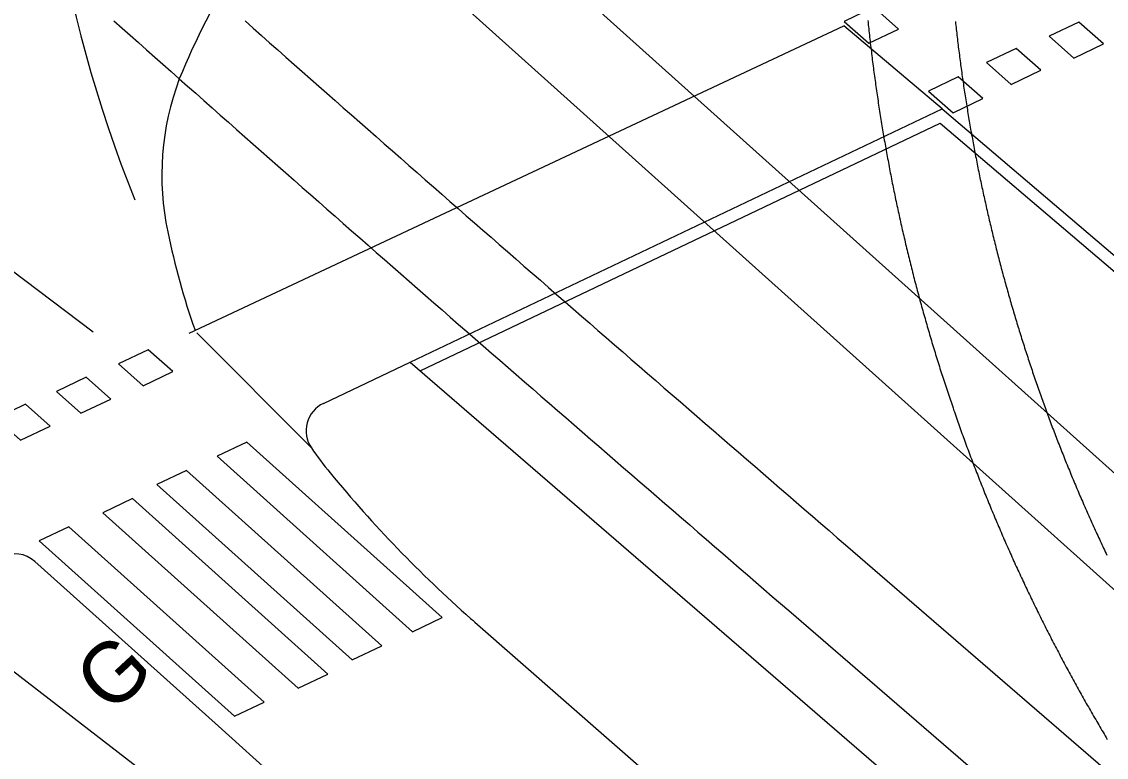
# Model space of a CAD drawing. Extents: x 81617 to 82144, y 454649 to 455150.
# Drawn here: x 81697.46 to 81715.37, y 454720.05 to 454732.19 of the extents above; entities that cross this region are included whole.
import ezdxf

# ---------------------------------------------------------------- set-up
doc = ezdxf.new("R2010")
doc.units = 0
doc.layers.add('B-WE-OG-TOPOGRAFIE-G', color=7, linetype='Continuous')
doc.layers.add('B-WE-VW-MARKERING-G', color=7, linetype='Continuous')

msp = doc.modelspace()

# ---------------------------------------------------------------- linework, layer by layer
at = {"layer": 'B-WE-OG-TOPOGRAFIE-G'}
for p, q in [((81712.656, 454730.753), (81711.029, 454732.123)), ((81703.871, 454726.575), (81712.656, 454730.753)), ((81712.656, 454730.753), (81722.86, 454722.067)), ((81704.037, 454726.432), (81712.624, 454730.516)), ((81712.624, 454730.516), (81722.73, 454721.915)), ((81702.24, 454725.16), (81700.349, 454727.06)), ((81702.438, 454725.893), (81703.871, 454726.575)), ((81703.871, 454726.575), (81730.855, 454703.267)), ((81700.649, 454720.614), (81697.672, 454723.285)), ((81699.533, 454719.756), (81696.366, 454722.2)), ((81704.288, 454717.349), (81700.649, 454720.614))]:
    msp.add_line(p, q, dxfattribs=at)
for points in [[(81733.293, 454708.784), (81733.175, 454708.889), (81733.058, 454708.994), (81732.94, 454709.1), (81732.94, 454709.1), (81698.035, 454740.405), (81698.035, 454740.405), (81697.901, 454740.525), (81697.766, 454740.646), (81697.632, 454740.766), (81697.498, 454740.887), (81697.364, 454741.007)], [(81733.393, 454706.767), (81733.276, 454706.872), (81733.158, 454706.977), (81733.04, 454707.083), (81732.923, 454707.188), (81732.805, 454707.294), (81732.688, 454707.399), (81732.57, 454707.504), (81732.452, 454707.61), (81732.335, 454707.715), (81732.217, 454707.821), (81732.1, 454707.926), (81731.982, 454708.032), (81731.982, 454708.032), (81697.077, 454739.337)], [(81698.978, 454732.209), (81699.113, 454732.089), (81699.248, 454731.969), (81699.383, 454731.849), (81699.518, 454731.729), (81699.653, 454731.609), (81699.788, 454731.49), (81699.923, 454731.37), (81700.058, 454731.25), (81700.194, 454731.131), (81700.329, 454731.011), (81700.464, 454730.891), (81700.599, 454730.772), (81700.735, 454730.652), (81700.87, 454730.533), (81701.005, 454730.413), (81701.141, 454730.294), (81701.276, 454730.174), (81701.412, 454730.055), (81701.547, 454729.935), (81701.683, 454729.816), (81701.818, 454729.697), (81701.954, 454729.577), (81702.089, 454729.458), (81702.225, 454729.339), (81702.36, 454729.22), (81702.496, 454729.101), (81702.632, 454728.981), (81702.767, 454728.862), (81702.903, 454728.743), (81703.039, 454728.624), (81703.175, 454728.505), (81703.31, 454728.386), (81703.446, 454728.267), (81703.582, 454728.148), (81703.718, 454728.03), (81703.854, 454727.911), (81703.99, 454727.792), (81704.126, 454727.673), (81704.262, 454727.554), (81704.398, 454727.436), (81704.534, 454727.317), (81704.67, 454727.198), (81704.806, 454727.08), (81704.806, 454727.079), (81704.942, 454726.961), (81705.078, 454726.842), (81705.214, 454726.724), (81705.351, 454726.605), (81705.487, 454726.487), (81705.623, 454726.369), (81705.759, 454726.25), (81705.895, 454726.132), (81706.031, 454726.014), (81706.168, 454725.895), (81706.304, 454725.777), (81706.44, 454725.659), (81706.576, 454725.541), (81706.713, 454725.423), (81706.849, 454725.304), (81706.985, 454725.186), (81707.122, 454725.068), (81707.258, 454724.95), (81707.394, 454724.832), (81707.531, 454724.714), (81707.667, 454724.596), (81707.804, 454724.478), (81707.94, 454724.36), (81708.076, 454724.242), (81708.213, 454724.124), (81708.349, 454724.006), (81708.486, 454723.888), (81708.622, 454723.77), (81708.758, 454723.652), (81708.895, 454723.534), (81709.031, 454723.416), (81709.168, 454723.299), (81709.304, 454723.181), (81709.441, 454723.063), (81709.577, 454722.945), (81709.713, 454722.827), (81709.85, 454722.709), (81709.986, 454722.591), (81710.123, 454722.473), (81710.123, 454722.473), (81759.251, 454680.037)], [(81701.145, 454732.205), (81701.28, 454732.086), (81701.415, 454731.966), (81701.55, 454731.847), (81701.685, 454731.728), (81701.82, 454731.608), (81701.955, 454731.489), (81702.09, 454731.37), (81702.225, 454731.25), (81702.36, 454731.131), (81702.496, 454731.012), (81702.631, 454730.893), (81702.766, 454730.774), (81702.901, 454730.655), (81703.037, 454730.536), (81703.172, 454730.417), (81703.308, 454730.298), (81703.443, 454730.179), (81703.578, 454730.06), (81703.714, 454729.941), (81703.849, 454729.822), (81703.985, 454729.703), (81704.12, 454729.585), (81704.256, 454729.466), (81704.392, 454729.347), (81704.527, 454729.228), (81704.663, 454729.11), (81704.798, 454728.991), (81704.934, 454728.872), (81705.07, 454728.754), (81705.206, 454728.635), (81705.341, 454728.517), (81705.477, 454728.398), (81705.613, 454728.28), (81705.749, 454728.161), (81705.749, 454728.161), (81705.885, 454728.043), (81706.021, 454727.925), (81706.157, 454727.806), (81706.292, 454727.688), (81706.428, 454727.57), (81706.564, 454727.452), (81706.7, 454727.334), (81706.836, 454727.215), (81706.972, 454727.097), (81707.108, 454726.979), (81707.244, 454726.861), (81707.381, 454726.743), (81707.517, 454726.625), (81707.653, 454726.507), (81707.789, 454726.389), (81707.925, 454726.271), (81708.061, 454726.153), (81708.197, 454726.035), (81708.334, 454725.917), (81708.47, 454725.799), (81708.606, 454725.681), (81708.742, 454725.563), (81708.879, 454725.445), (81709.015, 454725.327), (81709.151, 454725.209), (81709.288, 454725.092), (81709.424, 454724.974), (81709.56, 454724.856), (81709.697, 454724.738), (81709.833, 454724.62), (81709.97, 454724.502), (81710.106, 454724.384), (81710.242, 454724.266), (81710.379, 454724.149), (81710.515, 454724.031), (81710.652, 454723.913), (81710.788, 454723.795), (81710.924, 454723.677), (81711.061, 454723.559), (81711.061, 454723.559), (81760.224, 454681.093)], [(81711.428, 454732.213), (81711.432, 454732.178), (81711.435, 454732.144), (81711.439, 454732.11), (81711.443, 454732.076), (81711.446, 454732.042), (81711.45, 454732.008), (81711.454, 454731.974), (81711.458, 454731.939), (81711.462, 454731.905), (81711.465, 454731.871), (81711.469, 454731.837), (81711.473, 454731.803), (81711.477, 454731.769), (81711.481, 454731.735), (81711.486, 454731.701), (81711.49, 454731.666), (81711.494, 454731.632), (81711.498, 454731.598), (81711.502, 454731.564), (81711.507, 454731.53), (81711.511, 454731.496), (81711.515, 454731.462), (81711.52, 454731.428), (81711.524, 454731.394), (81711.529, 454731.36), (81711.533, 454731.326), (81711.538, 454731.292), (81711.543, 454731.258), (81711.547, 454731.224), (81711.552, 454731.19), (81711.557, 454731.156), (81711.561, 454731.122), (81711.566, 454731.088), (81711.571, 454731.054), (81711.576, 454731.02), (81711.581, 454730.986), (81711.586, 454730.952), (81711.591, 454730.918), (81711.596, 454730.884), (81711.601, 454730.85), (81711.606, 454730.816), (81711.612, 454730.782), (81711.617, 454730.748), (81711.622, 454730.714), (81711.627, 454730.68), (81711.633, 454730.646), (81711.638, 454730.612), (81711.644, 454730.578), (81711.649, 454730.544), (81711.655, 454730.51), (81711.66, 454730.477), (81711.666, 454730.443), (81711.671, 454730.409), (81711.677, 454730.375), (81711.683, 454730.341), (81711.689, 454730.307), (81711.694, 454730.273), (81711.7, 454730.239), (81711.706, 454730.206), (81711.712, 454730.172), (81711.718, 454730.138), (81711.724, 454730.104), (81711.73, 454730.07), (81711.736, 454730.037), (81711.742, 454730.003), (81711.748, 454729.969), (81711.755, 454729.935), (81711.761, 454729.901), (81711.767, 454729.868), (81711.773, 454729.834), (81711.78, 454729.8), (81711.786, 454729.766), (81711.793, 454729.733), (81711.799, 454729.699), (81711.806, 454729.665), (81711.812, 454729.631), (81711.819, 454729.598), (81711.826, 454729.564), (81711.832, 454729.53), (81711.839, 454729.497), (81711.846, 454729.463), (81711.853, 454729.429), (81711.859, 454729.396), (81711.866, 454729.362), (81711.873, 454729.328), (81711.88, 454729.295), (81711.887, 454729.261), (81711.894, 454729.228), (81711.901, 454729.194), (81711.909, 454729.16), (81711.916, 454729.127), (81711.923, 454729.093), (81711.93, 454729.06), (81711.937, 454729.026), (81711.945, 454728.992), (81711.952, 454728.959), (81711.96, 454728.925), (81711.967, 454728.892), (81711.975, 454728.858), (81711.982, 454728.825), (81711.99, 454728.791), (81711.997, 454728.758), (81712.005, 454728.724), (81712.013, 454728.691), (81712.02, 454728.657), (81712.028, 454728.624), (81712.036, 454728.591), (81712.044, 454728.557), (81712.052, 454728.524), (81712.06, 454728.49), (81712.068, 454728.457), (81712.076, 454728.423), (81712.084, 454728.39), (81712.092, 454728.357), (81712.1, 454728.323), (81712.108, 454728.29), (81712.116, 454728.257), (81712.125, 454728.223), (81712.133, 454728.19), (81712.141, 454728.157), (81712.15, 454728.123), (81712.158, 454728.09), (81712.167, 454728.057), (81712.175, 454728.023), (81712.184, 454727.99), (81712.192, 454727.957), (81712.201, 454727.924), (81712.209, 454727.89), (81712.218, 454727.857), (81712.227, 454727.824), (81712.236, 454727.791), (81712.244, 454727.758), (81712.253, 454727.724), (81712.262, 454727.691), (81712.271, 454727.658), (81712.28, 454727.625), (81712.289, 454727.592), (81712.298, 454727.559), (81712.307, 454727.525), (81712.316, 454727.492), (81712.325, 454727.459), (81712.335, 454727.426), (81712.344, 454727.393), (81712.353, 454727.36), (81712.363, 454727.327), (81712.372, 454727.294), (81712.381, 454727.261), (81712.391, 454727.228), (81712.4, 454727.195), (81712.41, 454727.162), (81712.419, 454727.129), (81712.429, 454727.096), (81712.439, 454727.063), (81712.448, 454727.03), (81712.458, 454726.997), (81712.468, 454726.964), (81712.478, 454726.931), (81712.487, 454726.898), (81712.497, 454726.865), (81712.507, 454726.832), (81712.517, 454726.8), (81712.527, 454726.767), (81712.537, 454726.734), (81712.547, 454726.701), (81712.557, 454726.668), (81712.568, 454726.635), (81712.578, 454726.603), (81712.588, 454726.57), (81712.598, 454726.537), (81712.609, 454726.504), (81712.619, 454726.472), (81712.629, 454726.439), (81712.64, 454726.406), (81712.65, 454726.373), (81712.661, 454726.341), (81712.671, 454726.308), (81712.682, 454726.275), (81712.693, 454726.243), (81712.703, 454726.21), (81712.714, 454726.177), (81712.725, 454726.145), (81712.735, 454726.112), (81712.746, 454726.08), (81712.757, 454726.047), (81712.768, 454726.014), (81712.779, 454725.982), (81712.79, 454725.949), (81712.801, 454725.917), (81712.812, 454725.884), (81712.823, 454725.852), (81712.834, 454725.819), (81712.845, 454725.787), (81712.857, 454725.754), (81712.868, 454725.722), (81712.879, 454725.689), (81712.89, 454725.657), (81712.902, 454725.625), (81712.913, 454725.592), (81712.925, 454725.56), (81712.936, 454725.527), (81712.948, 454725.495), (81712.959, 454725.463), (81712.971, 454725.43), (81712.982, 454725.398), (81712.994, 454725.366), (81713.006, 454725.333), (81713.018, 454725.301), (81713.029, 454725.269), (81713.041, 454725.237), (81713.053, 454725.204), (81713.065, 454725.172), (81713.077, 454725.14), (81713.089, 454725.108), (81713.101, 454725.076), (81713.113, 454725.043), (81713.125, 454725.011), (81713.137, 454724.979), (81713.149, 454724.947), (81713.162, 454724.915), (81713.174, 454724.883), (81713.186, 454724.851), (81713.198, 454724.819), (81713.211, 454724.787), (81713.223, 454724.755), (81713.236, 454724.723), (81713.248, 454724.691), (81713.261, 454724.659), (81713.273, 454724.627), (81713.286, 454724.595), (81713.298, 454724.563), (81713.311, 454724.531), (81713.324, 454724.499), (81713.337, 454724.467), (81713.349, 454724.435), (81713.362, 454724.403), (81713.375, 454724.371), (81713.388, 454724.34), (81713.401, 454724.308), (81713.414, 454724.276), (81713.427, 454724.244), (81713.44, 454724.212), (81713.453, 454724.181), (81713.466, 454724.149), (81713.479, 454724.117), (81713.493, 454724.086), (81713.506, 454724.054), (81713.519, 454724.022), (81713.532, 454723.991), (81713.546, 454723.959), (81713.559, 454723.927), (81713.573, 454723.896), (81713.586, 454723.864), (81713.6, 454723.832), (81713.613, 454723.801), (81713.627, 454723.769), (81713.64, 454723.738), (81713.654, 454723.706), (81713.668, 454723.675), (81713.681, 454723.643), (81713.695, 454723.612), (81713.709, 454723.58), (81713.723, 454723.549), (81713.737, 454723.518), (81713.751, 454723.486), (81713.765, 454723.455), (81713.779, 454723.423), (81713.793, 454723.392), (81713.807, 454723.361), (81713.821, 454723.329), (81713.835, 454723.298), (81713.849, 454723.267), (81713.863, 454723.236), (81713.878, 454723.204), (81713.892, 454723.173), (81713.906, 454723.142), (81713.921, 454723.111), (81713.935, 454723.08), (81713.95, 454723.048), (81713.964, 454723.017), (81713.979, 454722.986), (81713.993, 454722.955), (81714.008, 454722.924), (81714.022, 454722.893), (81714.037, 454722.862), (81714.052, 454722.831), (81714.066, 454722.8), (81714.081, 454722.769), (81714.096, 454722.738), (81714.111, 454722.707), (81714.126, 454722.676), (81714.141, 454722.645), (81714.156, 454722.614), (81714.171, 454722.583), (81714.186, 454722.552), (81714.201, 454722.521), (81714.216, 454722.49), (81714.231, 454722.46), (81714.246, 454722.429), (81714.262, 454722.398), (81714.277, 454722.367), (81714.292, 454722.336), (81714.307, 454722.306), (81714.323, 454722.275), (81714.338, 454722.244), (81714.354, 454722.214), (81714.369, 454722.183), (81714.385, 454722.152), (81714.4, 454722.122), (81714.416, 454722.091), (81714.431, 454722.061), (81714.447, 454722.03), (81714.463, 454721.999), (81714.479, 454721.969), (81714.494, 454721.938), (81714.51, 454721.908), (81714.526, 454721.877), (81714.542, 454721.847), (81714.558, 454721.817), (81714.574, 454721.786), (81714.59, 454721.756), (81714.606, 454721.725), (81714.622, 454721.695), (81714.638, 454721.665), (81714.654, 454721.634), (81714.67, 454721.604), (81714.686, 454721.574), (81714.703, 454721.543), (81714.719, 454721.513), (81714.735, 454721.483), (81714.752, 454721.453), (81714.768, 454721.423), (81714.784, 454721.392), (81714.801, 454721.362), (81714.817, 454721.332), (81714.834, 454721.302), (81714.851, 454721.272), (81714.867, 454721.242), (81714.884, 454721.212), (81714.9, 454721.182), (81714.917, 454721.152), (81714.934, 454721.122), (81714.951, 454721.092), (81714.968, 454721.062), (81714.984, 454721.032), (81715.001, 454721.002), (81715.018, 454720.972), (81715.035, 454720.942), (81715.052, 454720.913), (81715.069, 454720.883), (81715.086, 454720.853), (81715.103, 454720.823), (81715.121, 454720.793), (81715.138, 454720.764), (81715.155, 454720.734), (81715.172, 454720.704), (81715.19, 454720.675), (81715.207, 454720.645), (81715.224, 454720.615), (81715.242, 454720.586), (81715.259, 454720.556), (81715.276, 454720.526), (81715.294, 454720.497), (81715.312, 454720.467), (81715.329, 454720.438), (81715.347, 454720.408), (81715.364, 454720.379), (81715.382, 454720.349)], [(81712.873, 454732.197), (81712.877, 454732.164), (81712.88, 454732.132), (81712.884, 454732.099), (81712.887, 454732.067), (81712.891, 454732.035), (81712.895, 454732.002), (81712.899, 454731.97), (81712.902, 454731.937), (81712.906, 454731.905), (81712.91, 454731.873), (81712.914, 454731.84), (81712.918, 454731.808), (81712.922, 454731.775), (81712.926, 454731.743), (81712.93, 454731.711), (81712.934, 454731.678), (81712.939, 454731.646), (81712.943, 454731.614), (81712.947, 454731.581), (81712.951, 454731.549), (81712.956, 454731.517), (81712.96, 454731.484), (81712.964, 454731.452), (81712.969, 454731.42), (81712.973, 454731.387), (81712.978, 454731.355), (81712.982, 454731.323), (81712.987, 454731.29), (81712.992, 454731.258), (81712.996, 454731.226), (81713.001, 454731.193), (81713.006, 454731.161), (81713.01, 454731.129), (81713.015, 454731.097), (81713.02, 454731.064), (81713.025, 454731.032), (81713.03, 454731), (81713.035, 454730.968), (81713.04, 454730.935), (81713.045, 454730.903), (81713.05, 454730.871), (81713.055, 454730.839), (81713.06, 454730.806), (81713.066, 454730.774), (81713.071, 454730.742), (81713.076, 454730.71), (81713.081, 454730.678), (81713.087, 454730.645), (81713.092, 454730.613), (81713.098, 454730.581), (81713.103, 454730.549), (81713.109, 454730.517), (81713.114, 454730.485), (81713.12, 454730.452), (81713.125, 454730.42), (81713.131, 454730.388), (81713.137, 454730.356), (81713.142, 454730.324), (81713.148, 454730.292), (81713.154, 454730.26), (81713.16, 454730.228), (81713.166, 454730.195), (81713.172, 454730.163), (81713.178, 454730.131), (81713.184, 454730.099), (81713.19, 454730.067), (81713.196, 454730.035), (81713.202, 454730.003), (81713.208, 454729.971), (81713.214, 454729.939), (81713.221, 454729.907), (81713.227, 454729.875), (81713.233, 454729.843), (81713.24, 454729.811), (81713.246, 454729.779), (81713.252, 454729.747), (81713.259, 454729.715), (81713.265, 454729.683), (81713.272, 454729.651), (81713.279, 454729.619), (81713.285, 454729.587), (81713.292, 454729.555), (81713.299, 454729.523), (81713.305, 454729.491), (81713.312, 454729.459), (81713.319, 454729.427), (81713.326, 454729.395), (81713.333, 454729.364), (81713.34, 454729.332), (81713.347, 454729.3), (81713.354, 454729.268), (81713.361, 454729.236), (81713.368, 454729.204), (81713.375, 454729.172), (81713.382, 454729.141), (81713.389, 454729.109), (81713.396, 454729.077), (81713.404, 454729.045), (81713.411, 454729.013), (81713.418, 454728.982), (81713.426, 454728.95), (81713.433, 454728.918), (81713.441, 454728.886), (81713.448, 454728.854), (81713.456, 454728.823), (81713.463, 454728.791), (81713.471, 454728.759), (81713.478, 454728.727), (81713.486, 454728.696), (81713.494, 454728.664), (81713.502, 454728.632), (81713.509, 454728.601), (81713.517, 454728.569), (81713.525, 454728.537), (81713.533, 454728.506), (81713.541, 454728.474), (81713.549, 454728.442), (81713.557, 454728.411), (81713.565, 454728.379), (81713.573, 454728.348), (81713.581, 454728.316), (81713.59, 454728.284), (81713.598, 454728.253), (81713.606, 454728.221), (81713.614, 454728.19), (81713.623, 454728.158), (81713.631, 454728.127), (81713.64, 454728.095), (81713.648, 454728.064), (81713.656, 454728.032), (81713.665, 454728.001), (81713.674, 454727.969), (81713.682, 454727.938), (81713.691, 454727.906), (81713.699, 454727.875), (81713.708, 454727.843), (81713.717, 454727.812), (81713.726, 454727.78), (81713.735, 454727.749), (81713.743, 454727.718), (81713.752, 454727.686), (81713.761, 454727.655), (81713.77, 454727.623), (81713.779, 454727.592), (81713.788, 454727.561), (81713.797, 454727.529), (81713.806, 454727.498), (81713.816, 454727.467), (81713.825, 454727.435), (81713.834, 454727.404), (81713.843, 454727.373), (81713.853, 454727.341), (81713.862, 454727.31), (81713.871, 454727.279), (81713.881, 454727.248), (81713.89, 454727.217), (81713.9, 454727.185), (81713.909, 454727.154), (81713.919, 454727.123), (81713.929, 454727.092), (81713.938, 454727.061), (81713.948, 454727.029), (81713.958, 454726.998), (81713.967, 454726.967), (81713.977, 454726.936), (81713.987, 454726.905), (81713.997, 454726.874), (81714.007, 454726.843), (81714.017, 454726.812), (81714.027, 454726.78), (81714.037, 454726.749), (81714.047, 454726.718), (81714.057, 454726.687), (81714.067, 454726.656), (81714.077, 454726.625), (81714.087, 454726.594), (81714.098, 454726.563), (81714.108, 454726.532), (81714.118, 454726.501), (81714.129, 454726.47), (81714.139, 454726.44), (81714.149, 454726.409), (81714.16, 454726.378), (81714.17, 454726.347), (81714.181, 454726.316), (81714.191, 454726.285), (81714.202, 454726.254), (81714.213, 454726.223), (81714.223, 454726.193), (81714.234, 454726.162), (81714.245, 454726.131), (81714.256, 454726.1), (81714.267, 454726.069), (81714.277, 454726.039), (81714.288, 454726.008), (81714.299, 454725.977), (81714.31, 454725.946), (81714.321, 454725.916), (81714.332, 454725.885), (81714.343, 454725.854), (81714.355, 454725.824), (81714.366, 454725.793), (81714.377, 454725.762), (81714.388, 454725.732), (81714.399, 454725.701), (81714.411, 454725.67), (81714.422, 454725.64), (81714.433, 454725.609), (81714.445, 454725.579), (81714.456, 454725.548), (81714.468, 454725.518), (81714.479, 454725.487), (81714.491, 454725.457), (81714.503, 454725.426), (81714.514, 454725.396), (81714.526, 454725.365), (81714.538, 454725.335), (81714.549, 454725.304), (81714.561, 454725.274), (81714.573, 454725.243), (81714.585, 454725.213), (81714.597, 454725.183), (81714.609, 454725.152), (81714.621, 454725.122), (81714.633, 454725.091), (81714.645, 454725.061), (81714.657, 454725.031), (81714.669, 454725.001), (81714.681, 454724.97), (81714.693, 454724.94), (81714.705, 454724.91), (81714.718, 454724.879), (81714.73, 454724.849), (81714.742, 454724.819), (81714.755, 454724.789), (81714.767, 454724.759), (81714.779, 454724.728), (81714.792, 454724.698), (81714.804, 454724.668), (81714.817, 454724.638), (81714.83, 454724.608), (81714.842, 454724.578), (81714.855, 454724.548), (81714.868, 454724.518), (81714.88, 454724.488), (81714.893, 454724.458), (81714.906, 454724.428), (81714.919, 454724.398), (81714.931, 454724.368), (81714.944, 454724.338), (81714.957, 454724.308), (81714.97, 454724.278), (81714.983, 454724.248), (81714.996, 454724.218), (81715.009, 454724.188), (81715.023, 454724.158), (81715.036, 454724.128), (81715.049, 454724.098), (81715.062, 454724.069), (81715.075, 454724.039), (81715.089, 454724.009), (81715.102, 454723.979), (81715.115, 454723.949), (81715.129, 454723.92), (81715.142, 454723.89), (81715.156, 454723.86), (81715.169, 454723.831), (81715.183, 454723.801), (81715.196, 454723.771), (81715.21, 454723.742), (81715.224, 454723.712), (81715.237, 454723.682), (81715.251, 454723.653), (81715.265, 454723.623), (81715.279, 454723.594), (81715.292, 454723.564), (81715.306, 454723.534), (81715.32, 454723.505), (81715.334, 454723.475), (81715.348, 454723.446), (81715.362, 454723.416), (81715.376, 454723.387)], [(81704.937, 454722.283), (81708.662, 454719.021), (81727.987, 454702.211)]]:
    msp.add_lwpolyline(points, dxfattribs=at)
for centre, radius, start, end in [((81702.653, 454725.442), 0.5, 115.447, 214.308), ((81707.031, 454728.429), 5.8, 214.308, 219.418), ((81718.774, 454738.081), 21, 219.418, 228.5387), ((81697.338, 454722.913), 0.5, 48.0994, 115.447), ((81718.774, 454738.081), 21, 228.5387, 228.7857)]:
    msp.add_arc(centre, radius, start, end, dxfattribs=at)
at = {"layer": 'B-WE-VW-MARKERING-G'}
for p, q in [((81678.314, 454742.411), (81698.634, 454727.077)), ((81700.219, 454727.053), (81711.029, 454732.123))]:
    msp.add_line(p, q, dxfattribs=at)
for points in [[(81711.934, 454732.071), (81711.527, 454732.432), (81711.037, 454732.198), (81711.443, 454731.838)], [(81715.321, 454731.828), (81714.914, 454732.188), (81714.424, 454731.955), (81714.83, 454731.594)], [(81714.286, 454731.392), (81713.879, 454731.752), (81713.389, 454731.518), (81713.795, 454731.158)], [(81713.325, 454730.923), (81712.919, 454731.283), (81712.428, 454731.049), (81712.835, 454730.689)], [(81699.954, 454726.419), (81699.547, 454726.779), (81699.057, 454726.546), (81699.463, 454726.185)], [(81698.926, 454725.963), (81698.519, 454726.324), (81698.029, 454726.09), (81698.435, 454725.73)], [(81697.927, 454725.519), (81697.52, 454725.879), (81697.029, 454725.645), (81697.436, 454725.285)], [(81704.399, 454722.359), (81701.175, 454725.254), (81700.684, 454725.021), (81703.91, 454722.126)], [(81703.403, 454721.893), (81700.179, 454724.788), (81699.688, 454724.555), (81702.914, 454721.66)], [(81702.509, 454721.427), (81699.285, 454724.323), (81698.794, 454724.089), (81702.02, 454721.195)], [(81701.46, 454720.962), (81698.236, 454723.857), (81697.745, 454723.624), (81700.971, 454720.729)]]:
    msp.add_lwpolyline(points, close=True, dxfattribs=at)
for centre, radius, start, end in [((81719.891, 454737.529), 22.169, 149.9749, 201.9261), ((81711.569, 454726.522), 12.444, 138.3584, 157.6665), ((81704.271, 454729.664), 4.501, 159.3722, 192.0722), ((81711.577, 454731.089), 11.944, 191.4261, 199.5067)]:
    msp.add_arc(centre, radius, start, end, dxfattribs=at)

# ---------------------------------------------------------------- texts
at = {"layer": 'B-WE-OG-TOPOGRAFIE-G'}
msp.add_text('G', height=1, rotation=42.8465, dxfattribs=at).set_placement((81698.928, 454720.74))

doc.saveas('drawing.dxf')
